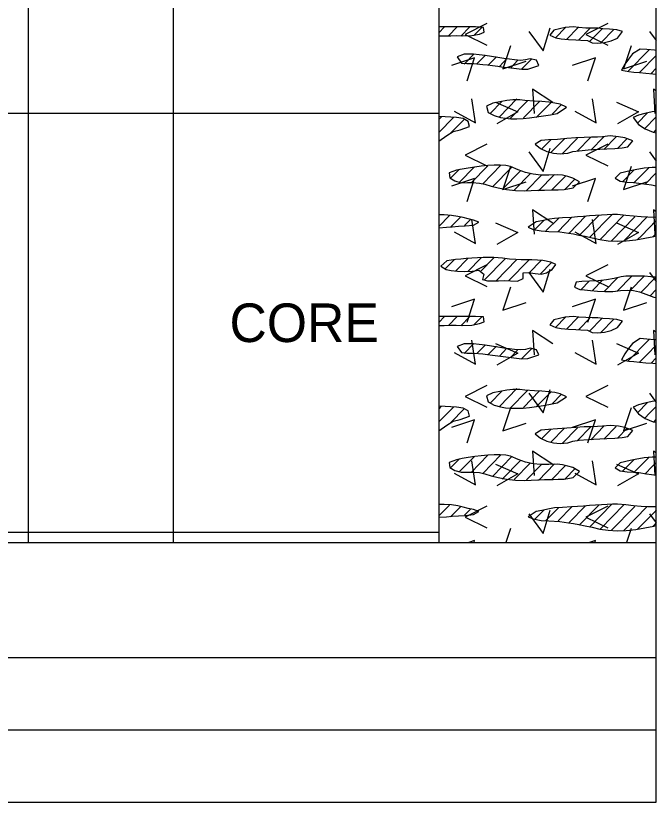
# Model space of a CAD drawing. Extents: x 0 to 0.833, y -0.32 to 0.608.
# Drawn here: x 0.7228 to 0.8333, y -0.32 to -0.1842 of the extents above; entities that cross this region are included whole.
import ezdxf

# ---------------------------------------------------------------- set-up
doc = ezdxf.new("R2010")
doc.units = 0

msp = doc.modelspace()

# ---------------------------------------------------------------- linework, layer by layer
for points in [[(0, -0.32004), (0.83333, -0.32004), (0.83333, 0.60833), (0, 0.60833)], [(0.79583, -0.1877), (0.79676, -0.18771), (0.79792, -0.18769), (0.79882, -0.18766), (0.79992, -0.1877), (0.80151, -0.18766), (0.80282, -0.1874), (0.80367, -0.18708), (0.80354, -0.18624), (0.80216, -0.18615), (0.79583, -0.18615)], [(0.81822, -0.18835), (0.81944, -0.18841), (0.82033, -0.18845), (0.82145, -0.18852), (0.82229, -0.18893), (0.82324, -0.18897), (0.82438, -0.18887), (0.82555, -0.18858), (0.82662, -0.18808), (0.82749, -0.18698), (0.82651, -0.18668), (0.82524, -0.18657), (0.82413, -0.18651), (0.82324, -0.1864), (0.82226, -0.18639), (0.82121, -0.18636), (0.81995, -0.18627), (0.81902, -0.18615), (0.81761, -0.18629), (0.81566, -0.18674), (0.81496, -0.18758), (0.81598, -0.18807), (0.81695, -0.18824)], [(0.83305, -0.1902), (0.83171, -0.19009), (0.83054, -0.18999), (0.82925, -0.19081), (0.82857, -0.19172), (0.82792, -0.19261), (0.82735, -0.19364), (0.82858, -0.19386), (0.82945, -0.19396), (0.83045, -0.19406), (0.83155, -0.19416), (0.83272, -0.19425), (0.83333, -0.1943), (0.83333, -0.19021)], [(0.80066, -0.19251), (0.80188, -0.19251), (0.80339, -0.19264), (0.80423, -0.19274), (0.8051, -0.19285), (0.806, -0.19297), (0.80692, -0.19309), (0.80784, -0.1932), (0.80875, -0.19331), (0.81014, -0.19346), (0.81119, -0.19344), (0.81222, -0.1931), (0.81308, -0.19281), (0.81267, -0.19191), (0.8116, -0.19166), (0.81075, -0.19186), (0.80989, -0.19195), (0.80885, -0.19187), (0.80799, -0.19175), (0.80703, -0.19161), (0.806, -0.19145), (0.80492, -0.19128), (0.80384, -0.19112), (0.8028, -0.19099), (0.80182, -0.1909), (0.8002, -0.19089), (0.79901, -0.19136), (0.79974, -0.1924)], [(0.81233, -0.19901), (0.81063, -0.19889), (0.80977, -0.19876), (0.8086, -0.19875), (0.80755, -0.1989), (0.80632, -0.19909), (0.80513, -0.19934), (0.80403, -0.19986), (0.80436, -0.20092), (0.80536, -0.20149), (0.80647, -0.20179), (0.8073, -0.20194), (0.80824, -0.20201), (0.80926, -0.20202), (0.81035, -0.20197), (0.81149, -0.20187), (0.81267, -0.20172), (0.81386, -0.20154), (0.81506, -0.20132), (0.81625, -0.20109), (0.81783, -0.20001), (0.81673, -0.19951), (0.81585, -0.19931), (0.8148, -0.19915), (0.81361, -0.19905)], [(0.83265, -0.20082), (0.83136, -0.20113), (0.83028, -0.20141), (0.82934, -0.2018), (0.83026, -0.203), (0.83142, -0.20376), (0.83279, -0.20434), (0.83333, -0.20444), (0.83333, -0.20073)], [(0.79583, -0.20592), (0.79719, -0.20493), (0.79831, -0.20423), (0.79951, -0.20396), (0.80111, -0.20336), (0.80086, -0.20247), (0.80002, -0.202), (0.79889, -0.2018), (0.79791, -0.20177), (0.79694, -0.20171), (0.79583, -0.20163)], [(0.82537, -0.20498), (0.82408, -0.20513), (0.82319, -0.20518), (0.82214, -0.20521), (0.82091, -0.20525), (0.81947, -0.20534), (0.81792, -0.20546), (0.81632, -0.20558), (0.81475, -0.20567), (0.81348, -0.20577), (0.81247, -0.20641), (0.81337, -0.20717), (0.81444, -0.20768), (0.81561, -0.20796), (0.81675, -0.20807), (0.81807, -0.20796), (0.81896, -0.20768), (0.82003, -0.20754), (0.82157, -0.20741), (0.82253, -0.20736), (0.82362, -0.2073), (0.82483, -0.20724), (0.82618, -0.20717), (0.82745, -0.20706), (0.82842, -0.20689), (0.82927, -0.20583), (0.82791, -0.20532), (0.82679, -0.20512)], [(0.79885, -0.21089), (0.79763, -0.21135), (0.79773, -0.21224), (0.79859, -0.21277), (0.7997, -0.21306), (0.80074, -0.21305), (0.80165, -0.21304), (0.80281, -0.21312), (0.80377, -0.21333), (0.80486, -0.21368), (0.80606, -0.21397), (0.80751, -0.21425), (0.80905, -0.21443), (0.81052, -0.21447), (0.81177, -0.21441), (0.81289, -0.21437), (0.81408, -0.21433), (0.81553, -0.21429), (0.81642, -0.21427), (0.81745, -0.21423), (0.81897, -0.21396), (0.82011, -0.21292), (0.81896, -0.21226), (0.8181, -0.21199), (0.81717, -0.21179), (0.81626, -0.21169), (0.81479, -0.21175), (0.81343, -0.21174), (0.8121, -0.21159), (0.8108, -0.21129), (0.80953, -0.21083), (0.8082, -0.21028), (0.80736, -0.21012), (0.8064, -0.21005), (0.80536, -0.21005), (0.80427, -0.21011), (0.80314, -0.21021), (0.80201, -0.21036), (0.8009, -0.21053), (0.79984, -0.21071)], [(0.83263, -0.21044), (0.83126, -0.21058), (0.82969, -0.21084), (0.82883, -0.21102), (0.82712, -0.21143), (0.82623, -0.2123), (0.82708, -0.21279), (0.82831, -0.21297), (0.82941, -0.21304), (0.83033, -0.21313), (0.83165, -0.21331), (0.83253, -0.21345), (0.83333, -0.21359), (0.83333, -0.21045)], [(0.79583, -0.22084), (0.79715, -0.22073), (0.79814, -0.22066), (0.79922, -0.22058), (0.80039, -0.2205), (0.80179, -0.22037), (0.80275, -0.21986), (0.80179, -0.21952), (0.80091, -0.2193), (0.80003, -0.21908), (0.79909, -0.21888), (0.79803, -0.21871), (0.79677, -0.21862), (0.79583, -0.21864)], [(0.82816, -0.22309), (0.82978, -0.22292), (0.83137, -0.22267), (0.8329, -0.22236), (0.83333, -0.22225), (0.83333, -0.21901), (0.83295, -0.21905), (0.83188, -0.21902), (0.83071, -0.21897), (0.82938, -0.21887), (0.82807, -0.2187), (0.82662, -0.21858), (0.82576, -0.21858), (0.82484, -0.21861), (0.82387, -0.21866), (0.82286, -0.21872), (0.82182, -0.2188), (0.82077, -0.21889), (0.81973, -0.21897), (0.81872, -0.21905), (0.81715, -0.21914), (0.81579, -0.21923), (0.81491, -0.21937), (0.81357, -0.21964), (0.8126, -0.21985), (0.81121, -0.22077), (0.8121, -0.22113), (0.81345, -0.22138), (0.81479, -0.22147), (0.81668, -0.22157), (0.81818, -0.22177), (0.81905, -0.22192), (0.82, -0.2221), (0.82107, -0.22231), (0.82225, -0.22257), (0.82357, -0.22286), (0.82501, -0.22308), (0.82656, -0.22315)], [(0.79708, -0.22807), (0.79794, -0.22825), (0.79904, -0.22836), (0.80028, -0.2284), (0.80156, -0.22834), (0.80274, -0.22819), (0.80361, -0.22885), (0.80338, -0.22975), (0.80422, -0.23002), (0.80517, -0.23003), (0.80613, -0.22998), (0.8072, -0.22995), (0.80818, -0.22998), (0.80939, -0.23005), (0.81037, -0.22959), (0.81038, -0.22864), (0.8113, -0.22858), (0.81244, -0.22876), (0.81346, -0.22887), (0.81438, -0.22861), (0.81539, -0.22807), (0.81601, -0.22716), (0.81517, -0.22679), (0.81374, -0.22651), (0.81285, -0.22642), (0.81187, -0.22636), (0.81, -0.22636), (0.8091, -0.22634), (0.808, -0.22627), (0.80678, -0.22611), (0.8053, -0.22598), (0.80443, -0.22597), (0.80349, -0.22598), (0.80251, -0.22602), (0.80152, -0.22608), (0.80054, -0.22616), (0.79959, -0.22625), (0.7987, -0.22635), (0.79722, -0.22658), (0.79614, -0.22745)], [(0.83241, -0.22929), (0.83129, -0.22923), (0.83017, -0.22919), (0.8291, -0.22919), (0.82811, -0.22923), (0.82728, -0.22931), (0.82608, -0.22961), (0.82476, -0.22984), (0.8233, -0.22998), (0.82183, -0.23006), (0.82051, -0.23012), (0.81951, -0.23022), (0.81922, -0.23108), (0.82013, -0.2315), (0.82097, -0.23155), (0.822, -0.23165), (0.82318, -0.23178), (0.82448, -0.23187), (0.82584, -0.23184), (0.82719, -0.23168), (0.82836, -0.23161), (0.8294, -0.23169), (0.83043, -0.23193), (0.83156, -0.23232), (0.83291, -0.23281), (0.83333, -0.23288), (0.83333, -0.22937)], [(0.79583, -0.2377), (0.79676, -0.23771), (0.79792, -0.23769), (0.79882, -0.23766), (0.79992, -0.2377), (0.80151, -0.23765), (0.80282, -0.2374), (0.80367, -0.23708), (0.80354, -0.23624), (0.80216, -0.23615), (0.79583, -0.23615)], [(0.81822, -0.23835), (0.81944, -0.23841), (0.82033, -0.23845), (0.82145, -0.23852), (0.82229, -0.23893), (0.82324, -0.23897), (0.82438, -0.23887), (0.82555, -0.23858), (0.82662, -0.23808), (0.82749, -0.23698), (0.82651, -0.23668), (0.82524, -0.23657), (0.82413, -0.23651), (0.82324, -0.2364), (0.82226, -0.23639), (0.82121, -0.23636), (0.81995, -0.23627), (0.81902, -0.23615), (0.81761, -0.23629), (0.81566, -0.23674), (0.81496, -0.23758), (0.81598, -0.23807), (0.81695, -0.23824)], [(0.83305, -0.2402), (0.83171, -0.24009), (0.83054, -0.23999), (0.82925, -0.24081), (0.82857, -0.24172), (0.82792, -0.24261), (0.82735, -0.24364), (0.82858, -0.24386), (0.82945, -0.24396), (0.83045, -0.24406), (0.83155, -0.24416), (0.83272, -0.24425), (0.83333, -0.2443), (0.83333, -0.24021)], [(0.80066, -0.24251), (0.80188, -0.24251), (0.80339, -0.24264), (0.80423, -0.24274), (0.8051, -0.24285), (0.806, -0.24297), (0.80692, -0.24309), (0.80784, -0.2432), (0.80875, -0.24331), (0.81014, -0.24346), (0.81119, -0.24344), (0.81222, -0.2431), (0.81308, -0.24281), (0.81267, -0.24191), (0.8116, -0.24166), (0.81075, -0.24186), (0.80989, -0.24195), (0.80885, -0.24187), (0.80799, -0.24175), (0.80703, -0.24161), (0.806, -0.24145), (0.80492, -0.24128), (0.80384, -0.24112), (0.8028, -0.24099), (0.80182, -0.2409), (0.8002, -0.24089), (0.79901, -0.24136), (0.79974, -0.2424)], [(0.81233, -0.24901), (0.81063, -0.24889), (0.80977, -0.24876), (0.8086, -0.24875), (0.80755, -0.2489), (0.80632, -0.24909), (0.80513, -0.24934), (0.80403, -0.24986), (0.80436, -0.25092), (0.80536, -0.25149), (0.80647, -0.25178), (0.8073, -0.25194), (0.80824, -0.25201), (0.80926, -0.25202), (0.81035, -0.25197), (0.81149, -0.25187), (0.81267, -0.25172), (0.81386, -0.25154), (0.81506, -0.25132), (0.81625, -0.25109), (0.81783, -0.25001), (0.81673, -0.24951), (0.81585, -0.24931), (0.8148, -0.24915), (0.81361, -0.24905)], [(0.83265, -0.25082), (0.83136, -0.25113), (0.83028, -0.25141), (0.82934, -0.2518), (0.83026, -0.253), (0.83142, -0.25376), (0.83279, -0.25434), (0.83333, -0.25444), (0.83333, -0.25073)], [(0.79583, -0.25592), (0.79719, -0.25493), (0.79831, -0.25423), (0.79951, -0.25396), (0.80111, -0.25336), (0.80086, -0.25247), (0.80002, -0.252), (0.79889, -0.2518), (0.79791, -0.25177), (0.79694, -0.25171), (0.79583, -0.25163)], [(0.82537, -0.25498), (0.82408, -0.25513), (0.82319, -0.25518), (0.82214, -0.25521), (0.82091, -0.25524), (0.81947, -0.25534), (0.81792, -0.25546), (0.81632, -0.25558), (0.81475, -0.25567), (0.81348, -0.25577), (0.81247, -0.25641), (0.81337, -0.25717), (0.81444, -0.25768), (0.81561, -0.25796), (0.81675, -0.25807), (0.81807, -0.25796), (0.81896, -0.25768), (0.82003, -0.25754), (0.82157, -0.25741), (0.82253, -0.25736), (0.82362, -0.2573), (0.82483, -0.25724), (0.82618, -0.25717), (0.82745, -0.25706), (0.82842, -0.25689), (0.82927, -0.25583), (0.82791, -0.25532), (0.82679, -0.25512)], [(0.79885, -0.26089), (0.79763, -0.26135), (0.79773, -0.26224), (0.79859, -0.26277), (0.7997, -0.26306), (0.80074, -0.26305), (0.80165, -0.26304), (0.80281, -0.26312), (0.80377, -0.26333), (0.80486, -0.26368), (0.80606, -0.26397), (0.80751, -0.26425), (0.80905, -0.26443), (0.81052, -0.26447), (0.81177, -0.26441), (0.81289, -0.26437), (0.81408, -0.26433), (0.81553, -0.26429), (0.81642, -0.26427), (0.81745, -0.26423), (0.81897, -0.26396), (0.82011, -0.26292), (0.81896, -0.26226), (0.8181, -0.26199), (0.81717, -0.26179), (0.81626, -0.26169), (0.81479, -0.26175), (0.81343, -0.26174), (0.8121, -0.26159), (0.8108, -0.26129), (0.80953, -0.26083), (0.8082, -0.26028), (0.80736, -0.26012), (0.8064, -0.26005), (0.80536, -0.26005), (0.80427, -0.26011), (0.80314, -0.26021), (0.80201, -0.26036), (0.8009, -0.26053), (0.79984, -0.26071)], [(0.83263, -0.26044), (0.83126, -0.26058), (0.82969, -0.26084), (0.82883, -0.26102), (0.82712, -0.26143), (0.82623, -0.2623), (0.82708, -0.26279), (0.82831, -0.26297), (0.82941, -0.26304), (0.83033, -0.26313), (0.83165, -0.26331), (0.83253, -0.26345), (0.83333, -0.26359), (0.83333, -0.26045)], [(0.79583, -0.27084), (0.79715, -0.27073), (0.79814, -0.27066), (0.79922, -0.27058), (0.80039, -0.2705), (0.80179, -0.27037), (0.80275, -0.26986), (0.80179, -0.26952), (0.80091, -0.2693), (0.80003, -0.26908), (0.79909, -0.26888), (0.79803, -0.26871), (0.79677, -0.26862), (0.79583, -0.26864)], [(0.82816, -0.27309), (0.82978, -0.27292), (0.83137, -0.27267), (0.8329, -0.27236), (0.83333, -0.27225), (0.83333, -0.26901), (0.83295, -0.26905), (0.83188, -0.26902), (0.83071, -0.26897), (0.82938, -0.26887), (0.82807, -0.2687), (0.82662, -0.26858), (0.82576, -0.26858), (0.82484, -0.26861), (0.82387, -0.26866), (0.82286, -0.26872), (0.82182, -0.2688), (0.82077, -0.26889), (0.81973, -0.26897), (0.81872, -0.26905), (0.81715, -0.26914), (0.81579, -0.26923), (0.81491, -0.26937), (0.81357, -0.26964), (0.8126, -0.26985), (0.81121, -0.27077), (0.8121, -0.27113), (0.81345, -0.27138), (0.81479, -0.27147), (0.81668, -0.27157), (0.81818, -0.27177), (0.81905, -0.27192), (0.82, -0.2721), (0.82107, -0.27231), (0.82225, -0.27257), (0.82357, -0.27286), (0.82501, -0.27308), (0.82656, -0.27315)]]:
    msp.add_lwpolyline(points, close=True)
for points in [[(0.725, 0.55417), (0.725, -0.27517)], [(0.75, 0.55417), (0.75, -0.27517)], [(0.75, 0.55417), (0.75, -0.27517)], [(0.79583, 0.55417), (0.79583, -0.27517)], [(0.725, 0.54167), (0.725, -0.27517)], [(0.83333, -0.27517), (0.83333, 0.50377)], [(0.80412, -0.18558), (0.80038, -0.18746), (0.80412, -0.18933)], [(0.82496, -0.18558), (0.82121, -0.18746), (0.82496, -0.18933)], [(0.79583, -0.18719), (0.79681, -0.18618)], [(0.79898, -0.18617), (0.79747, -0.18772)], [(0.80116, -0.18615), (0.79959, -0.18776)], [(0.80328, -0.18619), (0.80188, -0.18762)], [(0.81134, -0.18693), (0.81384, -0.1903), (0.81503, -0.1863)], [(0.8177, -0.18629), (0.81596, -0.18807)], [(0.81988, -0.18627), (0.81785, -0.18835)], [(0.82185, -0.18646), (0.81997, -0.18839)], [(0.824, -0.18647), (0.82178, -0.18875)], [(0.82601, -0.18663), (0.82378, -0.18891)], [(0.83217, -0.18693), (0.83333, -0.18849)], [(0.80818, -0.18942), (0.80687, -0.19342), (0.81087, -0.1921)], [(0.82901, -0.18942), (0.8277, -0.19342), (0.8317, -0.1921)], [(0.83217, -0.19008), (0.82844, -0.19389)], [(0.80188, -0.19085), (0.8002, -0.19257)], [(0.8038, -0.19109), (0.80237, -0.19256)], [(0.80575, -0.19131), (0.80429, -0.1928)], [(0.83333, -0.1911), (0.83052, -0.19398)], [(0.80069, -0.1955), (0.802, -0.1915), (0.798, -0.19281)], [(0.80758, -0.19164), (0.80627, -0.19299)], [(0.80941, -0.19198), (0.80816, -0.19326)], [(0.81188, -0.19167), (0.81016, -0.19342)], [(0.82152, -0.1955), (0.82284, -0.1915), (0.81884, -0.19281)], [(0.83333, -0.19331), (0.83245, -0.19421)], [(0.81551, -0.19922), (0.81201, -0.19691), (0.81226, -0.2011)], [(0.83333, -0.19723), (0.83284, -0.19691), (0.83309, -0.2011)], [(0.79847, -0.20071), (0.80215, -0.20271), (0.80153, -0.19858)], [(0.80465, -0.20113), (0.80667, -0.19905)], [(0.80562, -0.19916), (0.80946, -0.20084), (0.80581, -0.20291)], [(0.80626, -0.20169), (0.80928, -0.1986)], [(0.80809, -0.20203), (0.81111, -0.19893)], [(0.81041, -0.20186), (0.81318, -0.19903)], [(0.81264, -0.20179), (0.81518, -0.19919)], [(0.81536, -0.20122), (0.81699, -0.19955)], [(0.8193, -0.20071), (0.82299, -0.20271), (0.82236, -0.19858)], [(0.82645, -0.19916), (0.83029, -0.20084), (0.82664, -0.20291)], [(0.70417, -0.20108), (0.725, -0.20108)], [(0.725, -0.20108), (0.75, -0.20108)], [(0.75, -0.20108), (0.79583, -0.20108)], [(0.7963, -0.20167), (0.79583, -0.20216)], [(0.79834, -0.2018), (0.79583, -0.20437)], [(0.79786, -0.2045), (0.80023, -0.20208)], [(0.8301, -0.20279), (0.83184, -0.20101)], [(0.83131, -0.20376), (0.83333, -0.20169)], [(0.83285, -0.20439), (0.83333, -0.2039)], [(0.80412, -0.20642), (0.80038, -0.20829), (0.80412, -0.21017)], [(0.81519, -0.20561), (0.81354, -0.2073)], [(0.81514, -0.20787), (0.81748, -0.20547)], [(0.81709, -0.20809), (0.81974, -0.20537)], [(0.8197, -0.20763), (0.82203, -0.20523)], [(0.82496, -0.20642), (0.82121, -0.20829), (0.82496, -0.21017)], [(0.82202, -0.20747), (0.8243, -0.20513)], [(0.82431, -0.20733), (0.82644, -0.20514)], [(0.82663, -0.20717), (0.82834, -0.20542)], [(0, -0.20754), (0, -0.32004), (0.83333, -0.32004), (0.83333, -0.20754)], [(0.81134, -0.20776), (0.81384, -0.21113), (0.81503, -0.20713)], [(0.83217, -0.20776), (0.83333, -0.20932)], [(0.79933, -0.21301), (0.80195, -0.21032)], [(0.80142, -0.21308), (0.8043, -0.21013)], [(0.80653, -0.21005), (0.8034, -0.21327)], [(0.80506, -0.21378), (0.8084, -0.21036)], [(0.80818, -0.21025), (0.80687, -0.21425), (0.81087, -0.21294)], [(0.82901, -0.21025), (0.8277, -0.21425), (0.8317, -0.21294)], [(0.83203, -0.21049), (0.82949, -0.21309)], [(0.79938, -0.21075), (0.79786, -0.2123)], [(0.80997, -0.21096), (0.80675, -0.21426)], [(0.81164, -0.21146), (0.80884, -0.21433)], [(0.81353, -0.21174), (0.81094, -0.21439)], [(0.81303, -0.21446), (0.81579, -0.21163)], [(0.82751, -0.2129), (0.82945, -0.21092)], [(0.83138, -0.21337), (0.83333, -0.21136)], [(0.80069, -0.21633), (0.802, -0.21233), (0.798, -0.21364)], [(0.81534, -0.2143), (0.81768, -0.21191)], [(0.8176, -0.2142), (0.81934, -0.21242)], [(0.82152, -0.21633), (0.82284, -0.21233), (0.81884, -0.21364)], [(0.83333, -0.21358), (0.83333, -0.21358)], [(0.81551, -0.22006), (0.81201, -0.21774), (0.81226, -0.22193)], [(0.82569, -0.21859), (0.82184, -0.22253)], [(0.83333, -0.21807), (0.83284, -0.21774), (0.83309, -0.22193)], [(0.79765, -0.21873), (0.79583, -0.2206)], [(0.7996, -0.21895), (0.79786, -0.22073)], [(0.79847, -0.22154), (0.80215, -0.22354), (0.80153, -0.21941)], [(0.8013, -0.21942), (0.80027, -0.22048)], [(0.80562, -0.21999), (0.80946, -0.22168), (0.80581, -0.22374)], [(0.81392, -0.21958), (0.81235, -0.22119)], [(0.8143, -0.2214), (0.8165, -0.21916)], [(0.8164, -0.22147), (0.81879, -0.21902)], [(0.81829, -0.22175), (0.82114, -0.21883)], [(0.8193, -0.22154), (0.82299, -0.22354), (0.82236, -0.21941)], [(0.82004, -0.22217), (0.82346, -0.21867)], [(0.82775, -0.21869), (0.8237, -0.22284)], [(0.82964, -0.21896), (0.82557, -0.22314)], [(0.82645, -0.21999), (0.83029, -0.22168), (0.82664, -0.22374)], [(0.83173, -0.21903), (0.82774, -0.22312)], [(0.83333, -0.21961), (0.83078, -0.22222), (0.83012, -0.2229)], [(0.83281, -0.22236), (0.83333, -0.22182)], [(0.79844, -0.22639), (0.79691, -0.22796)], [(0.79871, -0.22833), (0.80085, -0.22614)], [(0.80083, -0.22837), (0.80311, -0.22603)], [(0.80534, -0.22596), (0.80299, -0.22837)], [(0.80367, -0.22988), (0.80732, -0.22614)], [(0.80571, -0.23), (0.80924, -0.22639)], [(0.81142, -0.22637), (0.80785, -0.23002)], [(0.81141, -0.2286), (0.81348, -0.22647)], [(0.80412, -0.22725), (0.80038, -0.22913), (0.80412, -0.231)], [(0.81134, -0.22859), (0.81384, -0.23197), (0.81503, -0.22797)], [(0.81528, -0.22684), (0.81331, -0.22886)], [(0.82496, -0.22725), (0.82121, -0.22913), (0.82496, -0.231)], [(0.82433, -0.23186), (0.82666, -0.22947)], [(0.82909, -0.22919), (0.82656, -0.23178)], [(0.82885, -0.23165), (0.83122, -0.22922)], [(0.83325, -0.22936), (0.83065, -0.23202)], [(0.83217, -0.22859), (0.83333, -0.23015)], [(0.82035, -0.23151), (0.82176, -0.23006)], [(0.82233, -0.23169), (0.82408, -0.2299)], [(0.80818, -0.23108), (0.80687, -0.23508), (0.81087, -0.23377)], [(0.82901, -0.23108), (0.8277, -0.23508), (0.8317, -0.23377)], [(0.83333, -0.23148), (0.83227, -0.23258)], [(0.80069, -0.23716), (0.802, -0.23316), (0.798, -0.23448)], [(0.82152, -0.23716), (0.82284, -0.23316), (0.81884, -0.23448)], [(0.79583, -0.23719), (0.79681, -0.23618)], [(0.79898, -0.23617), (0.79747, -0.23772)], [(0.80116, -0.23615), (0.79959, -0.23776)], [(0.80328, -0.23619), (0.80188, -0.23762)], [(0.8177, -0.23629), (0.81596, -0.23807)], [(0.81988, -0.23627), (0.81785, -0.23835)], [(0.82185, -0.23646), (0.81997, -0.23839)], [(0.824, -0.23647), (0.82178, -0.23875)], [(0.82601, -0.23663), (0.82378, -0.23891)], [(0.81551, -0.24089), (0.81201, -0.23858), (0.81226, -0.24276)], [(0.83333, -0.2389), (0.83284, -0.23858), (0.83309, -0.24276)], [(0.79847, -0.24237), (0.80215, -0.24437), (0.80153, -0.24025)], [(0.8193, -0.24237), (0.82299, -0.24437), (0.82236, -0.24025)], [(0.83217, -0.24008), (0.82844, -0.24389)], [(0.80188, -0.24085), (0.8002, -0.24257)], [(0.8038, -0.24109), (0.80237, -0.24256)], [(0.80575, -0.24131), (0.80429, -0.2428)], [(0.80562, -0.24083), (0.80946, -0.24251), (0.80581, -0.24457)], [(0.80758, -0.24164), (0.80627, -0.24299)], [(0.81188, -0.24167), (0.81016, -0.24342)], [(0.82645, -0.24083), (0.83029, -0.24251), (0.82664, -0.24457)], [(0.83333, -0.2411), (0.83177, -0.2427), (0.83052, -0.24398)], [(0.80941, -0.24198), (0.80816, -0.24326)], [(0.83333, -0.24331), (0.83245, -0.24421)], [(0.80412, -0.24808), (0.80038, -0.24996), (0.80412, -0.25183)], [(0.82496, -0.24808), (0.82121, -0.24996), (0.82496, -0.25183)], [(0.80465, -0.25113), (0.80667, -0.24905)], [(0.80626, -0.25169), (0.80928, -0.2486)], [(0.80809, -0.25203), (0.81111, -0.24893)], [(0.81041, -0.25186), (0.81318, -0.24903)], [(0.81134, -0.24943), (0.81384, -0.2528), (0.81503, -0.2488)], [(0.81264, -0.25179), (0.81518, -0.24919)], [(0.81536, -0.25122), (0.81699, -0.24955)], [(0.83217, -0.24943), (0.83333, -0.25099)], [(0.8301, -0.25279), (0.83184, -0.25101)], [(0.7963, -0.25167), (0.79583, -0.25216)], [(0.79834, -0.2518), (0.79583, -0.25437)], [(0.79786, -0.2545), (0.80023, -0.25208)], [(0.80818, -0.25192), (0.80687, -0.25592), (0.81087, -0.2546)], [(0.82901, -0.25192), (0.8277, -0.25592), (0.8317, -0.2546)], [(0.83131, -0.25376), (0.83225, -0.25279), (0.83333, -0.25169)], [(0.83285, -0.25439), (0.83333, -0.2539)], [(0.80069, -0.258), (0.802, -0.254), (0.798, -0.25531)], [(0.82152, -0.258), (0.82284, -0.254), (0.81884, -0.25531)], [(0.8197, -0.25763), (0.82203, -0.25523)], [(0.82202, -0.25747), (0.8243, -0.25513)], [(0.82431, -0.25733), (0.82644, -0.25514)], [(0.81519, -0.25561), (0.81354, -0.2573)], [(0.81514, -0.25787), (0.81748, -0.25547)], [(0.81709, -0.25809), (0.81974, -0.25537)], [(0.82663, -0.25717), (0.82834, -0.25542)], [(0.79938, -0.26075), (0.79786, -0.2623)], [(0.79933, -0.26301), (0.80195, -0.26032)], [(0.80142, -0.26308), (0.8043, -0.26013)], [(0.80653, -0.26005), (0.8034, -0.26327)], [(0.80506, -0.26378), (0.8084, -0.26036)], [(0.81551, -0.26172), (0.81201, -0.25941), (0.81226, -0.2636)], [(0.83203, -0.26049), (0.82949, -0.26309)], [(0.83333, -0.25973), (0.83284, -0.25941), (0.83309, -0.2636)], [(0.79847, -0.26321), (0.80215, -0.26521), (0.80153, -0.26108)], [(0.80562, -0.26166), (0.80946, -0.26334), (0.80581, -0.26541)], [(0.80997, -0.26096), (0.80675, -0.26426)], [(0.81164, -0.26146), (0.80884, -0.26433)], [(0.81353, -0.26174), (0.81094, -0.26439)], [(0.81303, -0.26446), (0.81579, -0.26163)], [(0.81534, -0.2643), (0.81768, -0.26191)], [(0.8193, -0.26321), (0.82299, -0.26521), (0.82236, -0.26108)], [(0.82645, -0.26166), (0.83029, -0.26334), (0.82664, -0.26541)], [(0.82751, -0.2629), (0.82945, -0.26092)], [(0.83138, -0.26337), (0.8327, -0.26201), (0.83333, -0.26136)], [(0.8176, -0.2642), (0.81934, -0.26242)], [(0.83333, -0.26358), (0.83333, -0.26358)], [(0.79765, -0.26873), (0.79583, -0.2706)], [(0.81829, -0.27175), (0.82114, -0.26883)], [(0.82004, -0.27217), (0.82346, -0.26867)], [(0.82569, -0.26859), (0.82184, -0.27253)], [(0.82775, -0.26869), (0.8237, -0.27284)], [(0.7996, -0.26895), (0.79786, -0.27073)], [(0.8013, -0.26942), (0.80027, -0.27048)], [(0.80412, -0.26892), (0.80038, -0.27079), (0.80412, -0.27267)], [(0.81134, -0.27026), (0.81384, -0.27363), (0.81503, -0.26963)], [(0.81392, -0.26958), (0.81235, -0.27119)], [(0.8143, -0.2714), (0.8165, -0.26916)], [(0.8164, -0.27147), (0.81879, -0.26902)], [(0.82496, -0.26892), (0.82121, -0.27079), (0.82496, -0.27267)], [(0.82964, -0.26896), (0.82557, -0.27314)], [(0.83173, -0.26903), (0.82774, -0.27312)], [(0.83333, -0.26961), (0.83308, -0.26987), (0.83012, -0.2729)], [(0.83217, -0.27026), (0.83316, -0.27159), (0.83333, -0.27182)], [(0.80818, -0.27275), (0.80739, -0.27517)], [(0.82901, -0.27275), (0.82822, -0.27517)], [(0.83281, -0.27236), (0.83318, -0.27198), (0.83333, -0.27182)], [(0.70417, -0.2734), (0.725, -0.2734)], [(0.725, -0.2734), (0.75, -0.2734)], [(0.75, -0.2734), (0.79583, -0.2734)], [(0.70417, -0.27517), (0.725, -0.27517)], [(0.725, -0.27517), (0.75, -0.27517)], [(0.75, -0.27517), (0.79583, -0.27517)], [(0.79583, -0.27517), (0.83333, -0.27517)], [(0.79583, -0.27517), (0.83333, -0.27517)], [(0.80189, -0.27517), (0.802, -0.27483), (0.80098, -0.27517)], [(0.82272, -0.27517), (0.82284, -0.27483), (0.82181, -0.27517)], [(0, -0.29504), (0.83333, -0.29504)], [(0, -0.30754), (0.83333, -0.30754)]]:
    msp.add_lwpolyline(points)

# ---------------------------------------------------------------- texts
msp.add_text('CORE', height=0.006667).set_placement((0.75971, -0.24058))

doc.saveas('drawing.dxf')
